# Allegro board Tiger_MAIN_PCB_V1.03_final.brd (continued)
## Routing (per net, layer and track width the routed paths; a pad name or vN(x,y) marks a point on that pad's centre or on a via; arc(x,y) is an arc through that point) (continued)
I2C_DATA3: length 2.2
  BOTTOM w0.109: R380.2 45.52,69.86 U22.95
IINA: length 6.3
  BOTTOM w0.508: R3130.1 R3131.1 R3133.1 R3132.1 90.63,94.36 CN41.2
IINA0: length 45.6
  TOP w0.406: v2(85.32,92.74) 86.58,94 89.17,94 90.73,92.44 98.79,92.44 99.52,91.7 v2(100.04,91.7) 110.53,91.7 112.15,93.32 117.8,93.32 119.17,91.94 119.17,89.04 119.56,88.64 U2529.1
  BOTTOM w0.406: v2(100.04,91.7) 99.81,91.47 R345.1 97.38,91.47 96.96,91.06 J5.1 ; R3130.2 v2(85.32,92.74)
IINA1: length 46.9
  TOP w0.406: v2(86.38,92.74) 86.85,93.21 89.08,93.21 90.49,91.8 98.49,91.8 99.15,91.14 v2(100.55,91.14) 111.19,91.14 112.68,92.63 117.63,92.63 118.52,91.74 118.52,88.81 119.33,87.99 U2529.2
  BOTTOM w0.406: R3131.2 v2(86.38,92.74) ; J5.2 95.12,90.21 95.55,89.78 96.8,89.78 97.54,90.52 R345.2 99.93,90.52 v2(100.55,91.14)
IINA2: length 39.3
  TOP w0.406: U2529.4 119.41,86.7 118.99,87.12 118.99,87.57 117.75,88.81 R3089.1 117.75,91.49 117.25,91.99 113.44,91.99 111.97,90.52 98.87,90.52 98.3,91.1 90.25,91.1 v2(88.99,92.36)
  BOTTOM w0.406: R3118.2 88.31,91.52 R3095.1 v2(88.99,92.36)
  BOTTOM w0.508: R3132.2 88.31,93.39 R3095.1
IINA3: length 38.8
  TOP w0.406: v2(86.71,91.52) 87.91,90.32 98.04,90.32 98.49,89.87 112.97,89.87 115.19,87.66 R3090.1 118.08,87.66 118.47,87.27 118.47,86.53 118.96,86.04 U2529.5
  BOTTOM w0.406: v2(86.71,91.52) R3097.2 87.36,91.52 R3095.2
  BOTTOM w0.508: R3133.2 87.36,93.38 R3095.2
IMVP8_PROCHOT*: length 4.5
  BOTTOM w0.109: U103.38 237.03,86.31 237.03,85.73 235.84,84.55 234.26,84.55 R685.1
IMVP_SVID_CLK: length 5.5
  BOTTOM w0.109: R715.1 233.6,84.06 235.74,84.06 237.37,85.69 U103.37
IMVP_SVID_DATA: length 3.8
  BOTTOM w0.109: R686.2 237.42,83.7 237.08,84.04 237.08,84.67 238.17,85.76 U103.35
INNER_MIC: length 50.2
  TOP w0.305: v2(15.54,11.1) 15.54,10.07 17.46,8.16 52.27,8.16 54.48,10.37 CN42.2 57.49,8.96 B1.1
  BOTTOM w0.203: v2(15.54,11.1) R3119.2 15.66,11.81 C2845.1 C2844.1
INT_SERIRQ: length 169.1
  TOP w0.076: 184.55,45.45 188.13,49.03 188.13,51.18 188.52,51.57 R93.1 189.08,51.57 190.41,52.9 191.83,52.9 193.08,54.15 193.08,55.56 192.97,55.67 U1.AY11
  TOP w0.102: 184.55,45.45 183.49,44.39 183.49,37.25 180.21,33.97 169.4,33.97 167.75,32.32 153.19,32.32 144.84,40.67 144.84,43.73 127.32,61.24 117,61.24 v2(116.76,61.49) ; CN16.12 72.38,66.68 v2(72.35,66.71)
  LAY6 w0.102: v2(116.76,61.49) 115.51,61.49 114.95,62.05 114.95,62.57 114.36,63.17 83.76,63.17 79.18,67.75 73.09,67.75 72.35,67.01 v2(72.35,66.71)
  BOTTOM w0.102: U22.5 65.17,68.66 66.16,69.64 71.16,69.64 72.35,68.45 v2(72.35,66.71)
ISETA: length 15.8
  TOP w0.305: R3101.2 R3100.2 R3099.2 124.44,81.78 122.69,81.78 ; 122.69,81.78 R638.2 ; 122.69,81.78 R3098.2
  TOP w0.406: R648.1 117.81,85.39 U2529.6 ; R648.1 117.7,84.15 120.08,81.78 R638.2 ; R648.1 R754.1
ISH_ALS_INT*: length 9.3
  TOP w0.076: U1.BA8 190.83,55.77 190.83,54.53 190.47,54.18 188.86,54.18 188.3,53.62 187.83,53.62 186.3,52.09 186.3,50.75 R114.2
ISH_GYRO1_IRQ*: length 11.5
  TOP w0.076: R115.2 185.49,49.11 186.24,49.11 186.5,49.37 186.5,52.03 187.83,53.35 188.28,53.35 188.93,54 190.53,54 190.99,54.46 190.99,55.35 191.03,55.39 191.03,55.4 191.16,55.53 191.16,55.95 190.86,56.26 U1.AY8
ISH_GYRO2_IRQ*: length 6.9
  TOP w0.076: U1.BB7 189.75,54.35 188.79,54.35 188.24,53.8 187.74,53.8 186.1,52.15 186.1,51.36 R113.2
ISOLATEB: length 5.1
  BOTTOM w0.102: R315.1 131.52,45.26 130.76,45.26 129.87,44.36 129.87,43.44 129.28,42.85 129.28,42.59 128.98,42.3 U9.26
ISW: length 2.7
  TOP w0.305: R3091.2 124.93,84.28 125.39,84.74 U2529.10
ITP_PMODE: length 17.3
  TOP w0.076: v2(191.47,74.95) 191.25,74.73 U1.E8
  TOP w0.109: R719.2 179.64,81.37 182.5,78.51 v2(182.5,76.55)
  LAY6 w0.102: v2(182.5,76.55) 185.36,76.55 186.87,75.04 190,75.04 190.31,75.36 191.07,75.36 v2(191.47,74.95)
KBC_FAN_SPEED: length 131.7
  TOP w0.102: v2(158.4,18.59) 158.77,18.22 C608.2 160.21,18.22 R607.2 161.48,19.49 Q47.3
  LAY6 w0.102: v2(54.74,51.93) 74.47,51.93 75.71,50.68 87.83,50.68 89.48,49.03 92.02,49.03 92.69,48.36 92.69,47.9 93.03,47.56 94.26,47.56 96.35,49.64 109.86,49.64 110.64,50.42 111.59,50.42 116.18,45.83 123.39,45.83 124.43,44.79 130.21,44.79 130.9,45.49 135.37,45.49 153.26,27.61 153.26,23.73 v2(158.4,18.59)
  BOTTOM w0.203: v2(54.74,51.93) 54.72,51.95 U22.47
L_BKLT_EN: length 82.1
  TOP w0.076: U1.R12 v2(192.81,69.01)
  TOP w0.109: U27.2 135.51,82.8 R455.1 135.52,81.97 R454.1 135.71,81.97 136.17,81.5 136.17,79.1 135.51,78.44 v2(135.51,77)
  LAY6 w0.076: v2(192.81,69.01) 192.28,68.48 183.91,68.48 183.33,69.07 181.59,69.07 181.41,69.25 176.13,69.25
  LAY6 w0.087: 176.13,69.25 173.22,69.25 171.52,70.95 167.47,70.95 166.58,70.06 155.48,70.06 152.89,67.47 144.38,67.47 141.95,65.05 135.39,65.05 v2(134.6,65.83)
  BOTTOM w0.109: v2(134.6,65.83) 134.6,71.66 135.12,72.18 135.12,76.6 v2(135.51,77)
L_BRIGHTNESS: length 88.9
  TOP w0.076: v2(192.17,69.01) 192.36,69.27 U1.R11
  TOP w0.109: Q76.1 135.94,86.02 135.54,85.62 135.54,84.62 136.56,83.6 136.56,78.79 135.91,78.14 135.91,77.21 v2(136.14,76.98)
  TOP w0.203: Q76.1 137.38,86.72 137.2,86.9 136.56,86.9 136.15,87.31 136.15,88.82 R3111.1 R3123.2
  LAY6 w0.076: v2(192.17,69.01) 192.17,68.85 191.99,68.66 183.98,68.66 183.37,69.27 181.71,69.27 181.54,69.44 176.13,69.44
  LAY6 w0.087: v2(135.18,65.85) 142.37,65.85 144.21,67.69 152.8,67.69 155.39,70.28 166.36,70.28 167.26,71.18 171.6,71.18 173.33,69.44 176.13,69.44
  BOTTOM w0.109: v2(135.18,65.85) 135.18,71.61 135.7,72.13 135.7,76.55 v2(136.14,76.98)
L_OUT+: length 7.3
  TOP w0.508: CN21.2 245.95,27.15 246.45,26.65 246.45,25.13 245.84,24.52 R628.2
L_OUT-: length 4.8
  TOP w0.508: R627.2 244.57,25.44 CN21.1
L_VDD_EN: length 87.2
  TOP w0.076: v2(192.84,67.95) 193.45,67.95 U1.U13
  LAY6 w0.076: v2(192.84,67.95) 192.49,68.3 183.76,68.3 183.19,68.87 181.49,68.87 181.29,69.08 176.39,69.08 176.27,68.96 176.13,68.96
  LAY6 w0.102: v2(133.96,65.82) 135.04,64.74 142,64.74 144.51,67.24 153.01,67.24 155.58,69.81 166.72,69.81 167.63,70.72 171.43,70.72 173.2,68.96 176.13,68.96
  BOTTOM w0.102: v2(133.96,65.82) 133.96,80.62 131.91,82.67 131.45,82.67 130.39,83.73 R440.2 129.76,85.24 129.23,85.77 U25.3
LAN_CLK_REQ*: length 100.8
  TOP w0.076: U1.AT10 191.82,58.59 v2(191.47,58.24)
  LAY6 w0.076: v2(191.47,58.24) 191.47,58.11 190.62,57.26 187.85,57.26 187.3,56.71 184.05,56.71 183.18,55.84
  LAY6 w0.102: v2(124.82,53.48) 124.88,53.54 145.88,53.54 147.6,51.81 153.98,51.81 156.61,54.44 157.85,54.44 158.62,53.68 159.53,53.68 159.67,53.82 172.48,53.82 172.75,53.55 180.89,53.55 183.18,55.84
  BOTTOM w0.102: v2(191.47,58.24) 191.09,57.86 191.09,57.86 190.97,57.74 190.26,57.74 190.06,57.95 184.14,57.95 179.38,53.18 175.02,53.18 R1.2 ; v2(124.82,53.48) 124.8,53.45 U9.16
LAN_CMT: length 1.7
  TOP w0.305: U11.21 104.22,34.02 R332.2
LAN_CMT1: length 1.6
  TOP w0.305: U11.15 104.9,39.96 104.9,39.96 R334.2
LAN_CT: length 1.7
  TOP w0.305: R331.2 104.3,31.05 U11.24
LAN_CT1: length 1.6
  TOP w0.305: U11.18 104.9,36.99 104.9,36.99 R333.2
LAN_N1: length 15.4
  TOP w0.305: v2(102.57,31.06) R331.1 ; R332.1 v2(102.57,34.03)
  TOP w0.406: C401.2 103.12,28.06 C400.2 103.12,28.63 C402.1 103.13,29.41 C399.1 103.35,30.41 R331.1 ; R334.1 R333.1 103.15,37.94 v2(102.74,37.52)
  BOTTOM w0.406: v2(102.57,31.06) 102.57,31.06 v2(102.57,34.03) 102.57,37.36 v2(102.74,37.52)
LAN_PCIE_CLK_DN: length 128.8
  TOP w0.076: v2(209.34,79.35) 209.48,79.5 209.69,79.5 209.82,79.37 209.82,78.06 209.44,77.68 209.44,77.32 209.48,77.22 209.48,77.03 209.44,76.94 209.44,76.69 209.58,76.21 209.58,76.08 209.62,76 209.87,75.74 U1.D40
  LAY6 w0.076: 189.9,79.97 189.91,79.97 189.92,79.98 194.57,79.98 195.14,80.55 196.84,80.55 198.6,82.32 199.63,82.32 200.06,81.89 202.09,81.89 202.84,82.63 204.05,82.63 206.57,80.12 207.59,80.12 208.14,79.57 209.12,79.57 v2(209.34,79.35)
  LAY6 w0.087: v2(127.06,76.13) 126.85,76.34 126.85,76.79 127.16,77.11 129.3,77.11 130.23,76.18 134.99,76.18 135.49,75.68 141.86,75.68 142.82,76.64 149.05,76.64 150.64,78.23 158.43,78.23 160.42,80.22 162.06,80.22 162.54,80.7 163.63,80.7 163.8,80.88 169.67,80.88 169.97,80.58 171.89,80.58 172.72,79.75 174.55,79.75 175.8,81 177.74,81 178.27,81.53 182.35,81.53 182.96,80.92 182.96,80.59 183.58,79.97 189.9,79.97
  BOTTOM w0.109: v2(127.06,76.13) 126.88,75.95 126.88,75.14 126.6,74.86 126.6,45.98 126.31,45.69 126.31,43.48 U9.20
LAN_PCIE_CLK_DP: length 128.8
  TOP w0.076: U1.C40 209.69,76.46 209.61,76.71 209.61,76.9 209.64,77 209.64,77.25 209.61,77.34 209.61,77.61 209.99,77.99 209.99,79.43 209.76,79.66 209.52,79.66 209.34,79.84 v2(209.34,79.95)
  LAY6 w0.076: v2(209.34,79.95) 209.12,79.74 208.21,79.74 207.66,80.29 206.63,80.29 204.12,82.8 202.77,82.8 202.02,82.05 200.13,82.05 199.7,82.48 198.53,82.48 196.77,80.72 195.07,80.72 194.5,80.15 189.92,80.15 189.91,80.15 189.9,80.15
  LAY6 w0.087: v2(126.45,76.13) 126.66,76.34 126.66,76.87 127.09,77.29 129.37,77.29 130.31,76.36 135.07,76.36 135.57,75.87 141.78,75.87 142.74,76.82 148.98,76.82 150.56,78.41 158.35,78.41 160.35,80.4 161.98,80.4 162.46,80.89 163.56,80.89 163.73,81.06 169.75,81.06 170.05,80.76 171.97,80.76 172.8,79.93 174.48,79.93 175.73,81.18 177.66,81.18 178.19,81.71 182.43,81.71 183.14,81 183.14,80.67 183.66,80.15 189.9,80.15
  BOTTOM w0.109: v2(126.45,76.13) 126.66,75.92 126.66,75.23 126.38,74.96 126.38,46.07 126.09,45.78 126.09,43.49 U9.19
LAN_PLT_RST#: length 10.6
  BOTTOM w0.203: U9.25 128.7,42.93 129.25,43.48 129.25,44.13 130.92,45.79 131.38,45.79 R317.1 132.58,45.47 134.89,45.47 135.27,45.09 136.09,45.09 136.26,44.92 U10.4
LAN_RST: length 67.2
  TOP w0.076: v2(180.09,63.97) 180.67,63.39 182.3,63.39 183.57,64.66 U1.AD1
  LAY6 w0.102: v2(180.09,63.97) 179.16,63.04 168.69,63.04 167.61,64.12 157.03,64.12 150.63,57.72 145.74,57.72 144.85,58.61 135.13,58.61 v2(134.77,58.25)
  BOTTOM w0.102: R318.2 v2(134.77,58.25)
LAN_TX0N: length 3.8
  TOP w0.097: U11.22 105.08,33.03 104.98,32.93 104.98,32.8 104.89,32.71 102.79,32.71 FIL1.1
LAN_TX0P: length 3.8
  TOP w0.097: U11.23 105.08,32.04 104.98,32.14 104.98,32.27 104.89,32.36 102.84,32.36 FIL1.4
LAN_TX1N: length 4
  TOP w0.097: FIL2.1 102.71,35.68 104.89,35.68 104.98,35.77 104.98,35.9 105.08,36 U11.19
LAN_TX1P: length 3.9
  TOP w0.097: U11.20 105.08,35.01 104.98,35.11 104.98,35.24 104.89,35.33 102.63,35.33 FIL2.4
LAN_TX2N: length 2.9
  TOP w0.097: U11.16 106.13,38.79 v2(107.06,38.79)
  BOTTOM w0.097: FIL3.4 105.79,38.66 106.93,38.66 v2(107.06,38.79)
LAN_TX2P: length 3
  TOP w0.097: v2(107.06,38.19) 106.16,38.19 U11.17
  BOTTOM w0.097: FIL3.1 105.86,38.32 106.93,38.32 v2(107.06,38.19)
LAN_TX3N: length 3
  TOP w0.097: v2(107.05,41.74) 106.15,41.74 U11.13
  BOTTOM w0.097: v2(107.05,41.74) 106.92,41.61 105.82,41.61 FIL4.4
LAN_TX3P: length 2.9
  TOP w0.097: v2(107.05,41.14) 106.14,41.14 U11.14
  BOTTOM w0.097: v2(107.05,41.14) 106.92,41.27 105.78,41.27 FIL4.1
LAN_VDDEN: length 144.5
  TOP w0.102: v2(117.35,44.28) 117.35,51.13 v2(119.75,53.53)
  LAY3 w0.102: v2(58.44,70.52) 57.8,69.88 57.8,61.11 v2(58.49,60.42)
  LAY6 w0.102: v2(171.73,54.46) 170.87,54.46 170.45,54.05 158.67,54.05 158.01,54.71 156.47,54.71 153.83,52.07 147.99,52.07 146.14,53.91 124.55,53.91 124.17,53.53 v2(119.75,53.53) 119.72,53.56 119.19,53.56 114.51,58.25 102.43,58.25 101.27,59.41 96.39,59.41 95.66,60.14 70.53,60.14 70.16,59.77 64.72,59.77 63.63,60.87 58.93,60.87 v2(58.49,60.42)
  BOTTOM w0.102: v2(58.44,70.52) 58.72,70.8 U22.124 ; v2(117.35,44.28) R309.2 U8.3 ; v2(171.73,54.46) 171.93,54.66 R142.1
LANWAKEB: length 4.6
  BOTTOM w0.102: R313.1 131.74,43.66 130.65,42.57 130.24,42.57 129.16,41.5 U9.28
LAO1_CLKN: length 20.3
  BOTTOM w0.109: CN35.8 137.87,95.67 137.76,95.56 137.43,95.56 137.27,95.4 137.27,94.88 136.85,94.46 135.87,94.46 132.62,91.21 132.62,84.56 134.04,83.14 135.23,83.14 136.02,83.92 136.37,83.92 136.46,84.01 U2526.35
LAO1_CLKP: length 20.2
  BOTTOM w0.109: U2526.34 136.46,83.61 136.37,83.7 136.11,83.7 135.33,82.92 133.95,82.92 132.4,84.47 132.4,91.3 135.78,94.67 136.75,94.67 137.05,94.97 137.05,95.5 136.87,95.67 CN35.9
LAO1_DATAN0: length 20.8
  LAY6 w0.087: v2(128.67,100.56) 128.62,100.56 128.25,100.2 128.25,98.93 136.08,91.1 136.08,90.82 v2(136.29,90.61)
  BOTTOM w0.109: CN35.24 128.87,101.47 128.76,101.36 128.59,101.36 128.48,101.25 128.48,100.76 v2(128.67,100.56) ; v2(136.29,90.61) 135.91,90.23 135.91,89.14 135.67,88.9 135.67,87.24 136.19,86.72 136.37,86.72 136.46,86.81 U2526.42
LAO1_DATAN1: length 19.4
  BOTTOM w0.109: U2526.40 136.46,86.01 136.37,85.92 135.98,85.92 134.62,87.28 134.62,90.79 136.71,92.88 142.08,92.88 143.26,94.06 143.26,95.38 143.45,95.56 143.76,95.56 143.87,95.67 CN35.2
LAO1_DATAN2: length 20.7
  BOTTOM w0.109: U2526.37 136.46,84.81 136.37,84.72 135.82,84.72 135.23,84.13 134.19,84.13 133.84,84.49 133.84,91.32 136.18,93.66 139.47,93.66 140.27,94.46 140.27,95.39 140.44,95.56 140.76,95.56 140.87,95.67 CN35.5
LAO1_DATAN3: length 20.3
  BOTTOM w0.109: U2526.32 136.46,82.81 136.37,82.72 135.94,82.72 135.52,82.3 133.8,82.3 131.88,84.22 131.88,91.56 135.28,94.95 135.28,95.41 135.43,95.56 135.76,95.56 135.87,95.67 CN35.10
LAO1_DATAP0: length 20.8
  LAY6 w0.087: v2(128.07,100.56) 128.07,98.85 135.9,91.02 135.9,90.81 v2(135.69,90.61)
  BOTTOM w0.109: CN35.23 127.87,101.47 127.98,101.36 128.15,101.36 128.26,101.25 128.26,100.76 v2(128.07,100.56) ; U2526.41 136.46,86.41 136.37,86.5 136.1,86.5 135.45,87.15 135.45,88.99 135.69,89.23 v2(135.69,90.61)
LAO1_DATAP1: length 19.4
  BOTTOM w0.109: CN35.3 142.87,95.67 143.05,95.5 143.05,94.15 141.99,93.1 136.62,93.1 134.4,90.88 134.4,87.19 135.89,85.7 136.37,85.7 136.46,85.61 U2526.39
LAO1_DATAP2: length 20.7
  BOTTOM w0.109: CN35.6 139.87,95.67 140.05,95.5 140.05,94.55 139.38,93.87 136.09,93.87 133.62,91.41 133.62,84.4 134.1,83.91 135.33,83.91 135.92,84.5 136.37,84.5 136.46,84.41 U2526.36
LAO1_DATAP3: length 20.3
  BOTTOM w0.109: CN35.11 134.87,95.85 135.06,95.66 135.06,95.04 131.66,91.65 131.66,84.13 133.71,82.08 135.61,82.08 136.03,82.5 136.37,82.5 136.46,82.41 U2526.31
LAO_CLKN: length 17.4
  LAY6 w0.087: v2(138.72,91.89) 138.51,92.1 138.51,94.83 134.47,98.88 134.47,100.36 v2(134.67,100.56)
  BOTTOM w0.109: CN35.30 134.87,101.47 134.76,101.36 134.59,101.36 134.48,101.25 134.48,100.76 v2(134.67,100.56) ; v2(138.72,91.89) 138.53,91.7 138.53,90.38 139.26,89.64 139.26,88.2 139.35,88.11 U2526.47
LAO_CLKP: length 17.4
  LAY6 w0.087: v2(138.12,91.89) 138.33,92.1 138.33,94.76 134.28,98.8 134.28,100.35 v2(134.07,100.56)
  BOTTOM w0.109: v2(134.07,100.56) 134.26,100.76 134.26,101.26 134.15,101.36 133.98,101.36 133.87,101.47 CN35.29 ; v2(138.12,91.89) 138.31,91.7 138.31,90.29 139.05,89.55 139.05,88.2 138.95,88.11 U2526.46
LAO_DATAN0: length 25.8
  BOTTOM w0.109: CN35.39 143.87,101.85 143.45,101.43 143.45,100.97 143.73,100.7 148.57,100.7 150.01,99.26 150.01,93.44 146.06,89.5 142.74,89.5 142.06,88.82 142.06,88.2 142.15,88.11 U2526.54
LAO_DATAN1: length 27.9
  BOTTOM w0.109: U2526.52 141.35,88.11 141.26,88.2 141.26,89.76 142.14,90.64 145.31,90.64 149.11,94.43 149.11,98.8 147.96,99.94 140.83,99.94 140.48,100.29 140.48,101.25 140.59,101.36 140.76,101.36 140.87,101.47 CN35.36
LAO_DATAN2: length 26.7
  BOTTOM w0.109: U2526.49 140.15,88.11 140.06,88.2 140.06,91.21 140.87,92.02 144.14,92.02 145.74,93.62 145.74,98.21 144.98,98.97 138.34,98.97 137.48,99.83 137.48,101.25 137.59,101.36 137.76,101.36 137.87,101.47 CN35.33
LAO_DATAN3: length 18.1
  LAY6 w0.087: v2(137.42,91.77) 137.21,91.98 137.21,93.04 131.46,98.8 131.46,100.36 v2(131.67,100.56)
  BOTTOM w0.109: CN35.27 131.87,101.47 131.76,101.36 131.59,101.36 131.48,101.25 131.48,100.76 v2(131.67,100.56) ; U2526.44 138.15,88.11 138.06,88.2 138.06,88.47 137.23,89.3 137.23,91.57 v2(137.42,91.77)
LAO_DATAP0: length 25.8
  BOTTOM w0.109: U2526.53 141.75,88.11 141.85,88.2 141.85,88.91 142.65,89.71 145.97,89.71 149.79,93.53 149.79,99.17 148.48,100.48 143.64,100.48 143.24,100.88 143.24,101.44 142.87,101.81 CN35.38
LAO_DATAP1: length 27.9
  BOTTOM w0.109: CN35.35 139.87,101.47 139.98,101.36 140.15,101.36 140.26,101.25 140.26,100.2 140.74,99.73 147.87,99.73 148.89,98.71 148.89,94.52 145.22,90.85 142.05,90.85 141.05,89.85 141.05,88.2 140.95,88.11 U2526.51
LAO_DATAP2: length 26.7
  BOTTOM w0.109: CN35.32 136.87,101.47 136.98,101.36 137.15,101.36 137.26,101.25 137.26,99.74 138.25,98.75 144.89,98.75 145.52,98.12 145.52,93.71 144.05,92.24 140.78,92.24 139.85,91.3 139.85,88.2 139.75,88.11 U2526.48
LAO_DATAP3: length 18.1
  LAY6 w0.087: v2(131.07,100.56) 131.28,100.36 131.28,98.72 137.03,92.97 137.03,91.98 v2(136.82,91.77)
  BOTTOM w0.109: v2(131.07,100.56) 131.26,100.76 131.26,101.26 131.15,101.36 130.98,101.36 130.87,101.47 CN35.26 ; v2(136.82,91.77) 137.01,91.57 137.01,89.21 137.85,88.38 137.85,88.2 137.75,88.11 U2526.43
LDO2-CAP: length 5.3
  BOTTOM w0.203: C444.2 10.55,23.37 12.02,23.37 13.13,22.26 U16.39
LDR: length 2.8
  TOP w0.305: U2529.11 127.17,85.39 127.42,85.14 127.42,84.31 127.78,83.96 R606.1
LED_ON: length 111.5
  TOP w0.102: R453.2 128.87,81.26 128.12,80.51 128.12,75.27 127.02,74.16 v2(127.02,72.79)
  LAY3 w0.102: v2(58.87,62.64) 58.87,73.01 57.9,73.97 57.9,83.89 v2(60.1,86.09)
  LAY6 w0.102: v2(127.02,72.79) 124.05,72.79 122.07,74.77 110.77,74.77 110.08,74.07 96.03,74.07 84.28,85.82 60.37,85.82 v2(60.1,86.09)
  BOTTOM w0.102: v2(58.87,62.64) 59.28,63.06 U22.19
LPC_CLKRUN*: length 181.1
  TOP w0.076: 190.32,53.33 191.68,53.33 192.54,54.2 192.54,54.49 192.39,54.64 192.39,56.32 192.7,56.63 U1.AW11 ; R94.2 187.72,51.17 187.72,49.27 184.64,46.19
  TOP w0.102: 181.65,36.18 183.03,37.55 183.03,44.58 184.64,46.19 ; R94.2 189.09,53.33 190.32,53.33
  TOP w0.109: 181.65,36.18 179.94,34.46 169.2,34.46 167.54,32.81 153.4,32.81 145.33,40.88 145.33,43.93 127.52,61.73 117.63,61.73 116.18,63.18 v2(115.78,63.18)
  LAY6 w0.087: v2(115.78,63.18) 115.39,63.57 84.85,63.57 78.75,69.68 63.63,69.68 62.91,68.96 48.46,68.96 v2(48.35,69.06)
  BOTTOM w0.109: U22.93 v2(48.35,69.06)
LPC_FRAME*: length 169.3
  TOP w0.076: 184.74,45.26 189.03,49.55 189.03,51.14 190.6,52.7 191.89,52.7 193.25,54.07 193.25,55.77 U1.BA12
  TOP w0.102: 184.74,45.26 183.95,44.47 183.95,37.21 182.92,36.18
  TOP w0.109: v2(70.86,69.22) 70.88,69.2 CN16.9 ; 182.92,36.18 180.44,33.7 169.52,33.7 167.86,32.04 153.08,32.04 144.56,40.56 144.56,43.61 127.2,60.96 116.5,60.96 115.77,61.69 v2(115.77,61.97)
  LAY6 w0.087: v2(70.86,69.22) 78.57,69.22 84.42,63.37 114.86,63.37 115.77,62.47 v2(115.77,61.97)
  BOTTOM w0.109: U22.6 65.25,68.26 66.22,69.22 v2(70.86,69.22)
LPC_LAD[0]: length 178.5
  TOP w0.076: 185.57,44.74 185.57,44.76 189.71,48.9 189.71,50.66 190.92,51.87 192.06,51.87 193.96,53.77 193.96,54.5 194.11,54.65 194.11,54.93 194.06,55.05 194.06,55.19 194.12,55.42 194.12,55.54 194.05,55.74 193.95,55.86 193.85,55.97 U1.AY13
  TOP w0.102: 185.57,44.74 185.57,37.05 184.69,36.18
  TOP w0.109: v2(70.45,66.8) 70.38,66.73 CN16.8 ; v2(69.53,64.14) 69.53,63.14 72,60.67 83.95,60.67 91.9,68.62 106.04,68.62 114.71,59.95 126.79,59.95 143.55,43.19 143.55,39.97 152.6,30.91 168.19,30.91 169.94,32.67 181.18,32.67 184.69,36.18
  BOTTOM w0.109: v2(69.53,64.14) 70.45,65.06 v2(70.45,66.8) 69.77,67.47 66.81,67.47 66,66.66 U22.10
LPC_LAD[1]: length 174.5
  TOP w0.076: U1.BA13 193.85,55.27 193.58,55 193.58,53.89 191.98,52.29 190.86,52.29 189.38,50.81 189.38,49.23 185.07,44.93
  TOP w0.102: 183.7,36.18 184.96,37.44 184.96,44.81 185.07,44.93
  TOP w0.109: v2(69.99,68.5) 70.01,68.47 70.01,66.31 69.88,66.18 CN16.7 69.88,64.98 73.68,61.18 83.74,61.18 91.69,69.13 106.25,69.13 114.92,60.46 127,60.46 144.06,43.4 144.06,40.35 152.87,31.54 168.07,31.54 169.73,33.2 180.72,33.2 183.7,36.18
  BOTTOM w0.109: v2(69.99,68.5) 69.2,67.71 66.48,67.71 65.83,67.06 U22.9
LPC_LAD[2]: length 174.3
  TOP w0.076: U1.BB13 193.76,54.73 193.76,53.82 192.04,52.1 190.91,52.1 189.54,50.73 189.54,49.06 185.25,44.76 185.25,44.75
  TOP w0.102: 184.18,36.18 185.25,37.24 185.25,44.75
  TOP w0.109: 184.18,36.18 180.94,32.93 169.84,32.93 168.18,31.28 152.76,31.28 143.79,40.24 143.79,43.29 126.89,60.2 114.81,60.2 106.15,68.87 91.8,68.87 83.85,60.92 73.35,60.92 69.38,64.89 CN16.6 69.38,66.12 69.16,66.34 69.16,68.31 v2(69.37,68.51)
  BOTTOM w0.109: v2(69.37,68.51) 68.81,67.95 66.12,67.95 65.62,67.46 U22.8
LPC_LAD[3]: length 178.2
  TOP w0.076: 184.89,45.11 189.2,49.42 189.2,50.97 190.73,52.51 191.94,52.51 193.41,53.98 193.41,55.36 193.58,55.53 193.58,55.95 193.28,56.26 U1.AY12
  TOP w0.102: 183.32,36.18 184.47,37.33 184.47,44.7 184.89,45.11
  TOP w0.109: 183.32,36.18 180.62,33.48 169.61,33.48 167.95,31.82 152.99,31.82 144.34,40.47 144.34,43.52 127.11,60.75 115.04,60.75 106.37,69.41 91.57,69.41 83.62,61.46 74.16,61.46 v2(71.46,64.17) ; v2(68.61,68.52) 68.88,68.25 CN16.5
  BOTTOM w0.109: v2(71.46,64.17) 71.17,64.45 71.17,68.09 70.29,68.97 69.05,68.97 v2(68.61,68.52) 66.04,68.52 65.38,67.86 U22.7
LPCPD#: length 2.4
  BOTTOM w0.109: U22.17 64.02,63.86 R488.2
M_B_A0: length 54.6
  TOP w0.076: 212.47,51.03 212.14,51.37 212.14,53.19 212.14,53.68 212.04,53.78 212.04,55.03 212.3,55.3 U1.BA46
  TOP w0.102: v2(214.64,45.39) 212.59,47.44 212.59,50.91 212.47,51.03
  TOP w0.153: 203.62,15.95 CN1.144
  TOP w0.165: v2(206.39,17.76) 205.43,17.76 203.62,15.95
  LAY6 w0.076: v2(214.64,45.39) 214.86,45.17
  LAY6 w0.137: v2(206.39,17.76) 205.96,18.19 205.96,19.4 206.37,19.81 206.37,25.83 209.85,29.31 209.85,34.13 210.36,34.64 210.55,34.64 211,34.19 211.2,34.19 211.39,34.38 211.39,34.58 210.94,35.03 210.94,35.22 211.13,35.42 211.33,35.42 211.78,34.97 211.97,34.97 212.17,35.16 212.17,35.35 211.71,35.81 211.71,36 211.91,36.2 212.1,36.2 212.56,35.74 212.75,35.74 212.95,35.94 212.95,36.13 212.49,36.58 212.49,36.78 212.69,36.97 212.88,36.97 213.33,36.52 213.53,36.52 213.72,36.71 213.72,36.91 213.27,37.36 213.27,37.55 214.86,39.15 214.86,45.17
M_B_A1: length 55.6
  TOP w0.076: U1.AY46 212.4,55.87 212.51,55.77 212.58,55.55 212.58,55.42 212.52,55.19 212.52,55.05 212.57,54.93 212.57,54.67 212.37,54.47 212.37,53.92 212.47,53.82 212.47,53.79 212.47,53.79 212.47,53.33 212.47,51.59 212.98,51.08 212.98,51.06
  TOP w0.102: 212.98,51.06 213.01,51.03 213.01,49 v2(214.66,47.34)
  TOP w0.165: v2(206.74,18.86) 206.36,19.23 CN1.133
  LAY6 w0.076: 215.54,45.27 215.21,45.6 215.21,46.8 v2(214.66,47.34)
  LAY6 w0.137: 215.54,45.27 215.54,37.07 215.4,36.93 215.4,35.63 215.33,35.56 215.13,35.56 214.84,35.85 214.65,35.85 214.45,35.65 214.45,35.46 214.74,35.17 214.74,34.98 214.09,34.33 214.09,34.14 214.8,33.43 214.8,33.24 214.6,33.05 214.41,33.05 213.71,33.75 213.51,33.75 213.32,33.55 213.32,33.36 214.02,32.66 214.02,32.46 213.83,32.27 213.63,32.27 212.93,32.97 212.74,32.97 212.54,32.78 212.54,32.58 213.24,31.88 213.24,31.69 213.05,31.49 212.86,31.49 212.15,32.19 211.96,32.19 211.77,32 211.77,31.81 212.47,31.11 212.47,30.91 212.27,30.72 212.08,30.72 211.38,31.42 211.18,31.42 210.86,31.09 210.86,29.1 207.28,25.52 207.28,22.93 206.95,22.6 206.95,19.07 v2(206.74,18.86)
M_B_A2: length 55.5
  TOP w0.076: 213.26,51.03 213.26,51.06 212.63,51.68 212.63,53.4 212.63,53.4 212.63,53.73 212.63,53.73 212.63,53.89 212.53,53.99 212.53,54.4 212.74,54.6 212.74,54.97 212.72,55 212.69,55.08 212.69,55.2 212.75,55.41 212.75,55.56 212.7,55.72 212.7,56.14 U1.AY47
  TOP w0.102: v2(214.66,47.99) 213.26,49.4 213.26,51.03
  TOP w0.153: CN1.132 206.62,15.91
  TOP w0.165: 206.62,15.91 207,16.3 v2(207.14,16.3)
  LAY6 w0.076: v2(214.66,47.99) 215.15,47.99 215.45,47.7 215.45,45.65 215.84,45.26
  LAY6 w0.137: 215.84,45.26 215.84,35.35 215.44,34.95 215.44,33.04 212.61,30.21 212.61,30.02 212.91,29.72 212.91,29.5 212.76,29.35 212.5,29.35 212.22,29.63 212.02,29.63 211.83,29.44 211.83,29.24 212.15,28.92 212.15,28.73 211.96,28.53 211.76,28.53 211.44,28.85 211.25,28.85 211.05,28.66 211.05,28.47 211.37,28.15 211.37,27.95 211.18,27.76 210.99,27.76 210.67,28.08 210.47,28.08 210.28,27.88 210.28,27.69 210.6,27.37 210.6,27.18 210.4,26.98 210.21,26.98 209.89,27.3 209.7,27.3 209.5,27.11 209.5,26.91 209.82,26.59 209.82,26.4 209.63,26.21 209.43,26.21 209.11,26.53 208.92,26.53 208.73,26.33 208.73,26.14 209.05,25.82 209.05,25.62 208.85,25.43 208.66,25.43 208.34,25.75 208.14,25.75 207.75,25.36 207.75,18.51 206.76,17.52 206.76,16.68 v2(207.14,16.3)
M_B_A3: length 53.8
  TOP w0.076: U1.BB46 212.2,54.72 212.2,53.85 212.3,53.75 212.3,53.26 212.3,53.26 212.3,51.47 212.74,51.03
  TOP w0.102: 212.74,51.03 212.78,50.99 212.78,47.91 v2(214.64,46.05)
  TOP w0.165: CN1.131 206.86,19.81 v2(207.35,19.33)
  LAY6 w0.076: 215.27,45.18 214.99,45.46 214.99,45.7 v2(214.64,46.05)
  LAY6 w0.137: 215.27,45.18 215.27,37.51 215.14,37.39 214.95,37.39 214.46,37.88 214.26,37.88 214.07,37.68 214.07,37.49 214.56,37 214.56,36.8 213.62,35.86 213.62,35.67 214.1,35.19 214.1,34.99 213.9,34.8 213.71,34.8 213.23,35.28 213.04,35.28 212.84,35.08 212.84,34.89 213.32,34.41 213.32,34.22 213.13,34.02 212.93,34.02 212.46,34.5 212.26,34.5 212.07,34.31 212.07,34.11 212.55,33.64 212.55,33.44 212.35,33.25 212.16,33.25 211.68,33.73 211.49,33.73 211.29,33.53 211.29,33.34 211.77,32.86 211.77,32.67 211.58,32.47 211.38,32.47 210.9,32.95 210.71,32.95 210.32,32.56 210.32,29.16 206.81,25.65 206.81,23.02 206.66,22.87 206.66,19.46 206.28,19.08 206.28,18.65 206.47,18.46 207.03,18.46 207.35,18.78 v2(207.35,19.33)
M_B_A4: length 54.7
  TOP w0.076: U1.BA47 213.19,55.58 213.19,55.35 213.2,55.34 213.2,55.34 213.2,55.34 213.23,55.25 213.23,55.05 213.2,54.96 213.2,54.56 213.32,54.43 213.32,53.82 213.42,53.73 213.42,53.33 213.52,53.23 213.52,53.2 213.53,53.19 213.53,51.99 214.03,51.5 214.03,51.49 214.03,50.79
  TOP w0.102: 214.03,50.79 213.52,50.27 213.52,49.56 213.99,49.09 214.46,49.09 v2(214.66,49.29)
  TOP w0.153: v2(207.19,16.94) 207.19,17.19 207.33,17.33 207.64,17.33 207.78,17.19 207.78,16.76 207.62,16.6 CN1.128
  LAY6 w0.076: v2(214.66,49.29) 214.95,49.58 215.44,49.58 215.64,49.37 215.64,45.74 216.08,45.3
  LAY6 w0.137: v2(207.19,16.94) 207.19,17.6 208.07,18.47 208.07,22.98 208.21,23.12 208.21,24.06 213.47,29.32 213.47,30.48 213.71,30.72 213.9,30.72 214.24,30.38 214.44,30.38 214.63,30.57 214.63,30.77 214.29,31.11 214.29,31.3 214.48,31.49 214.68,31.49 215.02,31.15 215.21,31.15 215.41,31.35 215.41,31.54 215.07,31.88 215.07,32.08 215.26,32.27 215.45,32.27 215.79,31.93 215.99,31.93 216.18,32.12 216.18,32.32 215.84,32.66 215.84,32.85 216.39,33.4 216.39,33.88 216.25,34.02 216.03,34.02 215.89,34.16 215.89,34.43 216.03,34.57 216.25,34.57 216.39,34.71 216.39,36.44 216.08,36.75 216.08,45.3
M_B_A5: length 55.5
  TOP w0.076: U1.AY48 213.43,55.92 213.43,55.76 213.36,55.57 213.36,55.37 213.4,55.28 213.4,55.02 213.36,54.93 213.36,54.67 213.49,54.55 213.49,53.89 213.58,53.79 213.58,53.4 213.7,53.29 213.7,52.08 214.11,51.68 214.11,51.66 214.21,51.56 214.21,50.58
  TOP w0.102: v2(214.66,49.94) 214.42,49.94 214.21,50.16 214.21,50.58
  TOP w0.153: 208.11,16.06 CN1.126
  TOP w0.165: v2(208.6,16.37) 208.43,16.37 208.11,16.06
  LAY6 w0.076: v2(214.66,49.94) 214.99,50.27 215.65,50.27 215.91,50.02 215.91,45.82 216.44,45.28
  LAY6 w0.137: v2(208.6,16.37) 208.31,16.37 208.15,16.2 208.15,14.52 207.78,14.16 207.02,14.16 206.85,14.33 206.85,14.56 207,14.71 207.43,14.71 207.62,14.91 207.62,17.52 208.39,18.28 208.39,22.32 208.7,22.64 208.7,23.94 216.86,32.09 216.86,36.55 216.44,36.97 216.44,45.28
M_B_A6: length 54.2
  TOP w0.076: v2(214.66,51.9) 214.44,51.9 214.05,52.28 214.05,53.46 213.94,53.58 213.94,53.92 213.9,53.96 213.9,54.98 213.63,55.25 U1.BA48
  TOP w0.153: CN1.127 207.86,18.3 208.49,17.67 209.15,17.67 209.35,17.88 209.35,18.27 v2(208.91,18.72)
  LAY6 w0.076: 217.12,45.17 216.31,45.98 216.31,51.12 215.54,51.9 v2(214.66,51.9)
  LAY6 w0.137: 217.12,45.17 217.12,37.31 217.75,36.69 217.75,30.44 217.36,30.06 217.17,30.06 216.74,30.49 216.54,30.49 216.35,30.3 216.35,30.1 216.78,29.67 216.78,29.47 216.59,29.28 216.39,29.28 215.96,29.71 215.77,29.71 215.57,29.52 215.57,29.33 216.01,28.89 216.01,28.7 215.81,28.5 215.62,28.5 215.18,28.94 214.99,28.94 214.8,28.74 214.8,28.55 215.23,28.12 215.23,27.92 209.56,22.25 209.56,18.73 209.39,18.56 209.06,18.56 v2(208.91,18.72)
M_B_A7: length 57.5
  TOP w0.076: U1.AP48 v2(214.33,59.51)
  TOP w0.153: CN1.122 209.11,16.88 209.26,17.03 210.03,17.03 210.29,16.76 210.29,16.32 210.16,16.19 209.83,16.19 v2(209.67,16.35)
  LAY6 w0.076: 217.9,45.32 217.36,45.87 217.36,51.78 215.07,54.07 215.07,57 214.71,57.35 214.71,59.14 v2(214.33,59.51)
  LAY6 w0.137: v2(209.67,16.35) 209.94,16.09 210.44,16.09 210.61,16.25 210.61,16.63 210.47,16.77 210.12,16.77 210,16.89 210,17.17 210.14,17.3 210.66,17.3 210.8,17.44 210.8,17.86 210.65,18.02 210.3,18.02 210.1,18.22 210.1,21.41 218.64,29.94 218.64,36.69 217.9,37.42 217.9,45.32
M_B_A8: length 52.6
  TOP w0.076: U1.BB48 213.63,54.64 213.65,54.62 213.65,53.96 213.75,53.86 213.75,53.47 213.86,53.36 213.86,52.15 214.27,51.75 214.27,51.73 214.37,51.63 214.37,51.63 214.44,51.57 214.44,51.47 v2(214.66,51.25)
  TOP w0.153: v2(208.89,19.39) 208.65,19.39 208.36,19.68 CN1.125
  LAY6 w0.076: v2(214.66,51.25) 215.53,51.25 216.14,50.64 216.14,45.86 216.72,45.28
  LAY6 w0.137: 216.72,45.28 216.72,37.21 217.3,36.62 217.3,31.89 214.09,28.68 214.09,28.48 214.52,28.06 214.52,27.87 214.32,27.67 214.13,27.67 213.71,28.1 213.51,28.1 213.32,27.9 213.32,27.71 213.74,27.28 213.74,27.09 213.55,26.9 213.35,26.9 212.93,27.32 212.74,27.32 212.54,27.12 212.54,26.93 212.96,26.51 212.96,26.32 212.77,26.12 212.58,26.12 212.15,26.54 211.96,26.54 211.76,26.35 211.76,26.15 212.19,25.73 212.19,25.54 211.99,25.34 211.8,25.34 211.38,25.77 211.18,25.77 210.99,25.57 210.99,25.38 211.41,24.96 211.41,24.76 211.22,24.57 211.02,24.57 210.6,24.99 210.41,24.99 210.21,24.8 210.21,24.6 210.63,24.18 210.63,23.99 210.44,23.79 210.25,23.79 209.82,24.21 209.63,24.21 209.14,23.72 209.14,22.74 209.28,22.6 209.28,19.77 v2(208.89,19.39)
M_B_A9: length 52.7
  TOP w0.076: U1.AP50 v2(215.25,59.51)
  TOP w0.153: CN1.121 209.36,18.87 210.14,18.09 210.86,18.09 211.05,18.28 211.05,18.83 v2(210.57,19.31)
  LAY6 w0.076: 218.5,45.73 218.5,46.64 218.51,46.66 218.51,51.86 215.29,55.08 215.29,57.01 214.88,57.42 214.88,59.14 v2(215.25,59.51)
  LAY6 w0.137: v2(210.57,19.31) 210.99,19.73 210.99,21.62 219.08,29.71 219.08,45.15 218.5,45.73
M_B_A10: length 54.9
  TOP w0.076: U1.AW46 212.4,56.59 212.21,56.4 212.11,56.19 212.11,55.7 211.87,55.46 211.87,53.71 211.97,53.62 211.97,53.12 211.97,51.26 212.2,51.03
  TOP w0.102: v2(212,46.71) 212.4,47.11 212.4,50.83 212.2,51.03
  TOP w0.153: CN1.146 v2(201.11,15.12)
  LAY6 w0.076: 212.46,44.67 212,45.14 v2(212,46.71)
  LAY6 w0.137: v2(201.11,15.12) 201.05,15.05 201.05,14.14 201.25,13.94 201.71,13.94 201.85,14.08 201.85,15.05 201.99,15.18 202.26,15.18 202.4,15.05 202.4,14.08 202.54,13.94 202.96,13.94 203.21,14.18 203.21,16.02 202.22,17.01 202.22,26.55 206.79,31.12 206.79,34.82 212.46,40.5 212.46,44.67
M_B_A11: length 58.1
  TOP w0.076: U1.AN48 v2(214.33,60.15)
  TOP w0.153: CN1.120 209.62,15.16
  TOP w0.165: 209.62,15.16 v2(209.61,15.17)
  LAY6 w0.076: v2(214.33,60.15) 214.08,60.15 213.88,59.94 213.88,57.51 214.71,56.67 214.71,54.05 217.11,51.65 217.11,45.55 217.49,45.17
  LAY6 w0.137: v2(209.61,15.17) 209.86,14.92 210.08,14.92 210.29,14.7 210.29,14.19 210.05,13.95 208.83,13.95 208.65,14.13 208.65,14.61 209.11,15.07 209.11,16.45 208.4,17.17 208.4,17.62 208.92,18.14 209.42,18.14 209.82,18.55 209.82,21.75 218.17,30.09 218.17,36.69 217.49,37.36 217.49,45.17
M_B_A12: length 57
  TOP w0.076: U1.AN50 v2(215.25,60.15)
  TOP w0.153: v2(210.56,18.55) 210.53,18.52 210.19,18.52 209.86,18.85 CN1.119
  LAY6 w0.076: 218.92,45.68 218.92,51.78 215.61,55.09 215.61,59.78 v2(215.25,60.15)
  LAY6 w0.137: v2(210.56,18.55) 210.65,18.46 211.12,18.46 211.26,18.6 211.26,21.13 219.58,29.45 219.58,31.64 219.71,31.78 220.09,31.78 220.22,31.92 220.22,32.19 220.09,32.33 219.71,32.33 219.58,32.46 219.58,32.74 219.71,32.88 220.09,32.88 220.22,33.01 220.22,33.29 220.09,33.42 219.71,33.42 219.58,33.56 219.58,33.84 219.71,33.97 220.09,33.97 220.22,34.11 220.22,34.38 220.09,34.52 219.71,34.52 219.58,34.66 219.58,34.93 219.71,35.07 220.09,35.07 220.22,35.21 220.22,35.48 220.09,35.62 219.71,35.62 219.58,35.76 219.58,36.03 219.71,36.17 220.09,36.17 220.22,36.3 220.22,36.58 220.09,36.72 219.71,36.72 219.58,36.85 219.58,45.03 218.92,45.68
M_B_A13: length 52.2
  TOP w0.076: U1.BA43 210.38,55.57 210.38,55.33 210.37,55.3 210.33,55.2 210.33,55.09 210.38,54.96 210.38,54.71 210.38,54.7 210.38,54.57 210.24,54.44 210.24,53.94 210.51,53.68 210.51,53.61 210.98,53.14 210.98,52.71 210.98,52.71 210.98,51.76 210.83,51.6 210.83,51.03
  TOP w0.102: v2(210.42,48.85) 210.66,48.85 210.83,49.02 210.83,51.03
  TOP w0.153: v2(199.71,17.5) 199.55,17.5 199.12,17.06 198.54,17.06 198.38,16.91 198.38,16.77 198.23,16.62 197.92,16.62 197.77,16.77 197.77,16.91 197.62,17.06 197.24,17.06 196.93,16.76 196.93,15.91 197.17,15.67 197.97,15.67 198.11,15.53 CN1.158
  LAY6 w0.076: 211.14,44.47 211,44.61 211,48.6 210.75,48.85 v2(210.42,48.85)
  LAY6 w0.137: v2(199.71,17.5) 199.98,17.5 200.13,17.65 200.13,21.6 199.94,21.79 199.94,27.16 204.72,31.94 204.72,35.37 211.14,41.79 211.14,44.47
M_B_ACT_N: length 54.9
  TOP w0.076: U1.AN53 v2(217.08,60.15)
  TOP w0.153: 211.11,15.69 CN1.114
  TOP w0.165: 211.11,15.69 211.36,15.93 211.56,15.93 v2(211.65,15.85)
  LAY6 w0.076: 221.7,50.27 218.55,53.42 218.55,55.51 216.7,57.36 216.7,59.77 v2(217.08,60.15)
  LAY6 w0.137: 221.7,50.27 221.72,50.25 221.72,29.53 212.83,20.65 212.83,18.93 210.97,17.06 210.97,15.92 211.14,15.74 211.55,15.74 v2(211.65,15.85)
M_B_BG0: length 56.4
  TOP w0.076: v2(216.16,59.51) 215.78,59.89 U1.AP52
  TOP w0.153: v2(211.87,18.58) 211.74,18.58 211.07,19.25 211.07,20.93 210.86,21.13 CN1.115
  LAY6 w0.076: 221,50.6 218.22,53.38 218.22,55.6 216.51,57.31 216.51,59.16 v2(216.16,59.51)
  LAY6 w0.137: 221,50.6 221.3,50.3 221.3,49.32 221.17,49.18 220.73,49.18 220.59,49.04 220.59,48.77 220.73,48.63 221.17,48.63 221.3,48.49 221.3,48.22 221.17,48.08 220.65,48.08 220.52,47.94 220.52,47.67 220.65,47.53 221.17,47.53 221.3,47.39 221.3,47.12 221.17,46.98 220.65,46.98 220.52,46.85 220.52,46.57 220.65,46.43 221.17,46.43 221.3,46.3 221.3,46.02 221.17,45.89 220.65,45.89 220.52,45.75 220.52,45.47 220.65,45.34 221.17,45.34 221.3,45.2 221.3,29.76 212.51,20.98 212.51,19.22 v2(211.87,18.58)
M_B_BG1: length 56.6
  TOP w0.076: U1.AN52 215.77,60.54 v2(216.16,60.15)
  TOP w0.153: v2(211.83,19.29) 211.61,19.29 211.36,19.53 CN1.113
  LAY6 w0.076: 220.87,44.2 219.36,45.72 219.36,51.67 215.78,55.25 215.78,59.77 v2(216.16,60.15)
  LAY6 w0.137: 220.87,44.2 220.87,42.39 220.69,42.2 220.34,42.2 220.2,42.07 220.2,41.79 220.34,41.65 220.73,41.65 220.87,41.52 220.87,41.24 220.73,41.11 220.21,41.11 220.07,40.97 220.07,40.69 220.21,40.56 220.73,40.56 220.87,40.42 220.87,40.14 220.73,40.01 220.21,40.01 220.07,39.87 220.07,39.6 220.21,39.46 220.73,39.46 220.87,39.32 220.87,39.05 220.73,38.91 220.21,38.91 220.07,38.77 220.07,38.5 220.21,38.36 220.73,38.36 220.87,38.22 220.87,37.95 220.73,37.81 220.21,37.81 220.07,37.68 220.07,37.4 220.21,37.26 220.73,37.26 220.87,37.13 220.87,31.86 220.02,31.01 220.02,29.3 212.25,21.53 212.25,19.71 v2(211.83,19.29)
M_B_BS0: length 53.1
  TOP w0.076: 211.4,51.03 211.4,51.25 211.48,51.32 211.48,52.92 211.48,52.92 211.48,53.38 211.38,53.48 211.38,53.48 211.38,53.62 211.38,54.72 U1.BB44
  TOP w0.102: 211.4,51.03 211.4,48.44 211.77,48.07 v2(212,48.07)
  TOP w0.153: v2(201.1,16.92) 201.26,16.76 202.33,16.76 202.67,17.1 202.67,18 202.46,18.22 200.59,18.22 200.11,17.75 CN1.150
  LAY6 w0.076: v2(212,48.07) 211.53,47.61 211.53,45.17 212.11,44.6
  LAY6 w0.137: 212.11,44.6 212.11,40.81 206.3,35.01 206.3,31.29 201.76,26.74 201.76,17.14 201.54,16.92 v2(201.1,16.92)
M_B_BS1: length 55.2
  TOP w0.076: 211.59,51.03 211.59,51.15 211.64,51.2 211.64,52.99 211.64,53.45 211.54,53.55 211.54,55.21 U1.BA44
  TOP w0.102: v2(212,48.73) 211.75,48.73 211.59,48.89 211.59,51.03
  TOP w0.153: CN1.145 201.36,20.84 201.47,20.73 201.88,20.73 202.04,20.89 202.04,22.06 202.19,22.21 202.82,22.21 202.95,22.08 202.95,19.44 202.77,19.26 202.48,19.26 202.32,19.41 202.32,19.91 202.17,20.06 201.86,20.06 201.71,19.91 201.71,19.41 201.56,19.26 201.1,19.26 v2(200.91,19.45)
  LAY6 w0.076: v2(212,48.73) 212,48.86 211.78,49.08 211.56,49.08 211.37,48.89 211.37,44.96 211.76,44.56
  LAY6 w0.137: v2(200.91,19.45) 201.21,19.45 201.33,19.57 201.33,21.89 201.19,22.03 200.99,22.03 200.86,22.16 200.86,22.44 200.99,22.58 201.19,22.58 201.33,22.71 201.33,22.99 201.19,23.12 200.99,23.12 200.86,23.26 200.86,23.54 200.99,23.67 201.19,23.67 201.33,23.81 201.33,24.08 201.19,24.22 200.99,24.22 200.86,24.36 200.86,24.63 200.99,24.77 201.19,24.77 201.33,24.91 201.33,25.18 201.19,25.32 200.99,25.32 200.86,25.46 200.86,25.73 200.99,25.87 201.19,25.87 201.33,26.01 201.33,26.92 205.83,31.43 205.83,35.21 211.76,41.14 211.76,44.56
M_B_CAS_N: length 56.2
  TOP w0.076: 211.02,51.03 211.02,51.52 211.15,51.65 211.15,52.78 211.15,52.78 211.15,53.21 211.03,53.33 211.03,54.41 210.84,54.59 210.84,54.97 210.86,55 210.89,55.08 210.89,55.2 210.83,55.41 210.83,55.56 210.88,55.72 210.88,55.9 210.81,56.06 210.81,56.16 U1.AY43
  TOP w0.102: v2(210.42,48.2) 210.84,47.79 210.84,45.22 210.94,45.12 211.28,45.12 211.41,45.25 211.41,47.68 211.02,48.07 211.02,51.03
  TOP w0.153: 198.62,15.94 CN1.156
  TOP w0.165: 198.62,15.94 198.99,16.32 v2(199.64,16.32)
  LAY6 w0.076: 210.81,44.34 210.81,47.82 v2(210.42,48.2)
  LAY6 w0.137: 210.81,44.34 210.81,42.18 204.3,35.67 204.3,32.24 199.43,27.37 199.43,21.81 199.85,21.39 199.85,18.86 199.24,18.25 199.24,16.72 199.64,16.33 v2(199.64,16.32)
M_B_CB0: length 3.1
  TOP w0.102: CN1.92 216.62,15.25 v2(216.11,15.75)
  BOTTOM w0.254: R490.2 216.62,15.75 v2(216.11,15.75)
M_B_CB1: length 2.9
  TOP w0.102: CN1.91 v2(216.86,20.22)
  BOTTOM w0.102: R492.2 216.86,21.28 v2(216.86,20.22)
M_B_CB2: length 5.4
  TOP w0.102: CN1.101 214.36,20.29 v2(213.4,19.33)
  BOTTOM w0.102: R493.2 214.25,20.18 v2(213.4,19.33)
M_B_CB3: length 2.1
  TOP w0.102: CN1.105 v2(213.36,20.61)
  BOTTOM w0.102: R494.2 213.36,21.33 v2(213.36,20.61)
M_B_CB4: length 4.8
  TOP w0.102: CN1.88 217.62,15.77 216.47,16.92 v2(216.11,16.92)
  BOTTOM w0.254: v2(216.11,16.92) 216.77,16.92 R495.2
M_B_CB5: length 2.9
  TOP w0.102: CN1.87 v2(217.86,20.22)
  BOTTOM w0.102: v2(217.86,20.22) 217.86,21.31 R496.2
M_B_CB6: length 2.1
  TOP w0.102: CN1.100 v2(214.62,15.16)
  BOTTOM w0.254: R497.2 215.13,15.16 v2(214.62,15.16)
M_B_CB7: length 4
  TOP w0.102: CN1.104 213.62,16.42 v2(213.11,16.92)
  BOTTOM w0.254: R501.2 212.45,16.92 v2(213.11,16.92)
M_B_CKE<0>: length 52.6
  TOP w0.076: U1.AN56 v2(218.91,60.15)
  TOP w0.153: CN1.109 212.36,23.14
  TOP w0.165: 212.36,23.14 212.36,24.99 212.72,25.34 213.28,25.34 213.5,25.12 213.5,24.84 213.65,24.68 213.98,24.68 214.16,24.86 214.16,25.18 214.32,25.34 214.66,25.34 214.82,25.18 214.82,24.84 214.97,24.68 215.3,24.68 215.48,24.86 215.48,25.18 215.65,25.34 215.98,25.34 216.14,25.18 216.14,24.84 216.3,24.68 216.63,24.68 216.81,24.86 216.81,25.18 216.97,25.34 217.3,25.34 217.47,25.18 217.47,24.84 217.62,24.68 217.95,24.68 218.13,24.86 218.13,25.18 218.29,25.34 v2(219.18,25.34)
  LAY6 w0.076: 222.81,49.87 218.93,53.76 218.93,56.13 218.55,56.5 218.55,59.8 v2(218.91,60.15)
  LAY6 w0.137: 222.81,49.87 222.98,49.7 222.98,29.14 v2(219.18,25.34)
M_B_CKE<1>: length 52.2
  TOP w0.076: U1.AP55 v2(217.99,59.51)
  TOP w0.153: CN1.110 212.11,17.29 v2(214.05,19.22)
  LAY6 w0.076: 222.18,50.19 218.76,53.61 218.76,55.65 218.34,56.07 218.34,59.16 v2(217.99,59.51)
  LAY6 w0.137: v2(214.05,19.22) 214.05,21.22 222.18,29.35 222.18,50.19
M_B_CLK_DDR_DN*<0>: length 54.3
  TOP w0.076: U1.AN45 v2(212.51,60.15)
  TOP w0.102: v2(204.36,19.45) 204.6,19.21 204.89,19.21 205.17,19.49 205.17,20.78 204.86,21.09 CN1.139
  LAY6 w0.076: v2(212.51,60.15) 212.51,60.03 212.31,59.84 212.12,59.84 211.96,59.67 211.96,57.27 212.17,57.06 212.17,56.03 212.1,55.95 211.82,55.95 211.64,55.77 211.64,55.48 211.8,55.32 212.07,55.32 212.16,55.23 212.16,55.08 212.1,55.01 211.77,55.01 211.6,54.84 211.6,54.55 211.77,54.38 212.1,54.38 212.17,54.3 212.17,54.15 212.1,54.07 211.77,54.07 211.6,53.9 211.6,53.61 211.77,53.44 212.16,53.44 212.24,53.36 212.24,53.21 212.16,53.14 211.77,53.14 211.6,52.96 211.6,52.67 211.77,52.5 212,52.5 212.17,52.33 212.17,51.87 213.06,50.98 213.06,45.28 213.06,45.13 213.1,45.1 213.1,45.09 213.11,45.08
  LAY6 w0.087: v2(204.36,19.45) 204.6,19.21 204.71,19.21 204.85,19.36 204.85,20.78 204.23,21.4 204.23,22.89 204.85,23.51 204.85,26.35 208.36,29.85 208.36,34.58 210.08,36.3 210.09,36.3 213.67,39.89 213.67,44.52 213.11,45.08
M_B_CLK_DDR_DN*<1>: length 53.4
  TOP w0.076: v2(213.42,60.15) 213.03,60.54 U1.AN46 ; v2(205.62,16.33) 205.39,16.11 205.07,16.11 204.78,15.82 204.78,15.08 204.62,14.91 CN1.140
  LAY6 w0.076: v2(213.42,60.15) 213.25,59.98 213.06,59.98 212.86,59.78 212.86,56.51 214.05,55.32 214.05,51.18 213.91,51.05 213.91,45.16
  LAY6 w0.087: v2(205.62,16.33) 205.75,16.2 206.1,16.2 206.17,16.26 206.17,16.93 205.24,17.86 205.24,22.13 205.54,22.43 205.54,26.04 209.12,29.62 209.12,34.39 211.03,36.3 211.04,36.3 214.22,39.47 214.22,44.86 213.91,45.16
M_B_CLK_DDR_DP<0>: length 54.3
  TOP w0.076: U1.AP45 212.13,59.89 v2(212.51,59.51)
  TOP w0.102: v2(204.36,18.86) 204.52,19.02 204.97,19.02 205.36,19.41 CN1.137
  LAY6 w0.076: v2(212.51,59.51) 212.35,59.67 212.19,59.67 212.12,59.6 212.12,57.34 212.34,57.13 212.34,55.96 212.16,55.79 211.89,55.79 211.8,55.7 211.8,55.55 211.87,55.48 212.14,55.48 212.32,55.3 212.32,55.01 212.16,54.85 211.84,54.85 211.77,54.77 211.77,54.62 211.84,54.54 212.16,54.54 212.34,54.37 212.34,54.08 212.16,53.91 211.84,53.91 211.77,53.83 211.77,53.68 211.84,53.6 212.23,53.6 212.4,53.43 212.4,53.14 212.23,52.97 211.84,52.97 211.77,52.89 211.77,52.74 211.84,52.67 212.07,52.67 212.34,52.4 212.34,51.94 213.23,51.05 213.23,45.21 213.23,45.21
  LAY6 w0.087: 213.23,45.21 213.85,44.59 213.85,39.81 208.54,34.51 208.54,29.77 205.04,26.27 205.04,23.44 204.41,22.82 204.41,21.47 205.03,20.85 205.03,19.29 204.78,19.04 204.54,19.04 v2(204.36,18.86)
M_B_CLK_DDR_DP<1>: length 53.4
  TOP w0.076: CN1.138 205.11,14.91 204.95,15.08 204.95,15.75 205.14,15.95 205.42,15.95 v2(205.62,15.75) ; U1.AP46 213.09,59.9 213.41,59.64 v2(213.42,59.51)
  LAY6 w0.076: 214.08,45.24 214.08,45.24 214.08,50.98 214.21,51.11 214.21,55.39 213.02,56.58 213.02,59.71 213.12,59.81 213.29,59.81 213.42,59.68 v2(213.42,59.51)
  LAY6 w0.087: v2(205.62,15.75) 205.89,16.02 206.18,16.02 206.34,16.19 206.34,17 205.42,17.93 205.42,22.06 205.72,22.36 205.72,23.44 205.73,23.44 205.73,25.97 209.3,29.54 209.3,34.31 214.39,39.4 214.39,44.93 214.08,45.24
M_B_CS*<0>: length 53.2
  TOP w0.076: U1.BB42 209.91,54.79 209.91,53.81 210.05,53.67 210.05,53.45 210.18,53.32 210.18,52.18 210.24,52.12 210.47,52.12 210.54,52.19 v2(210.54,52.3)
  TOP w0.153: v2(197.87,18.13) 198.32,17.69 199.04,17.69 200.36,19.01 CN1.149
  LAY6 w0.076: 208.84,45.03 209.11,45.3 209.11,51.08 210.33,52.3 v2(210.54,52.3)
  LAY6 w0.137: v2(197.87,18.13) 197.87,17.04 197.63,16.8 197.17,16.8 196.9,17.07 196.9,23.86 196.36,24.39 196.36,27.16 202.21,33.02 202.21,36.18 208.84,42.81 208.84,45.03
M_B_CS*<1>: length 54.6
  TOP w0.076: 209.84,51.24 209.84,53.19 209.72,53.31 209.72,53.53 209.58,53.67 209.58,54.42 209.52,54.48 209.52,54.97 209.53,54.99 209.62,55.21 209.68,55.37 209.68,55.86 U1.AY42
  TOP w0.102: 209.84,51.24 209.84,50.31 210,50.15 v2(210.42,50.15)
  TOP w0.153: v2(197.86,20.03) 198.36,20.53 CN1.157
  LAY6 w0.076: 209.86,44.29 209.62,44.52 209.62,50.47 209.78,50.63 210.07,50.63 210.42,50.28 v2(210.42,50.15)
  LAY6 w0.137: 209.86,44.29 209.86,42.57 203.14,35.86 203.14,32.63 198.42,27.91 198.42,20.52 198.93,20.01 198.93,16.23 198.65,15.95 198.19,15.95 198,16.14 198,16.45 198.27,16.73 198.27,19.62 v2(197.86,20.03)
M_B_DQ<0>: length 60
  TOP w0.076: U1.AY39 208.68,55.92 208.94,55.65 208.94,55.37 209.05,55.12 209.05,55.1 209.11,54.97 209.11,54.57 209.05,54.51 209.05,53.66 208.9,53.51 208.9,52.92 209.05,52.76 209.05,51.12 209.17,50.99 209.17,50.86 209.17,48.23 208.67,47.74 208.67,46.97 v2(207.97,46.27)
  TOP w0.129: CN1.8 237.61,15.25 v2(238.11,15.75)
  LAY3 w0.076: 207.97,45.5 v2(207.97,46.27)
  LAY3 w0.087: v2(238.11,15.75) 238.05,15.75 237.7,16.1 237.7,16.68 236.3,18.08 236.3,24.12 223.42,37 216.46,37 210.09,43.38
  LAY3 w0.091: 210.09,43.38 209.74,43.73
  LAY3 w0.094: 209.74,43.73 207.97,45.5
M_B_DQ<1>: length 58.1
  TOP w0.076: v2(207.97,52.23) 207.58,52.62 207.58,54.39 207.78,54.59 207.78,54.96 207.73,55.08 207.73,55.2 207.8,55.41 207.8,55.56 207.74,55.72 207.74,55.9 207.76,55.94 207.76,56.51 208.02,56.78 U1.AW39
  TOP w0.129: CN1.7 237.86,20.53 v2(237.37,20.03)
  LAY3 w0.076: 208.78,45.94 208.78,51.41 v2(207.97,52.23)
  LAY3 w0.087: 210.99,43.73 211.17,43.73 213.99,40.92 216.91,40.92 216.99,40.83 216.99,40.65 217.08,40.56 217.25,40.56 217.34,40.65 217.34,40.83 217.43,40.92 217.6,40.92 217.69,40.83 217.69,40.65 217.77,40.56 217.95,40.56 218.03,40.65 218.03,40.83 218.12,40.92 218.29,40.92 218.38,40.83 218.38,40.65 218.47,40.56 218.64,40.56 218.73,40.65 218.73,40.83 218.81,40.92 220.85,40.92 237.72,24.04 237.72,20.29 237.46,20.03 v2(237.37,20.03)
  LAY3 w0.091: 210.99,43.73 208.78,45.94
M_B_DQ<2>: length 60.3
  TOP w0.076: v2(207.97,51.58) 207.41,52.13 207.41,54.46 207.62,54.66 207.62,54.93 207.56,55.05 207.56,55.19 207.62,55.42 207.62,55.55 207.55,55.77 207.55,56.02 U1.AY37
  TOP w0.129: v2(234.36,20.62) 234.37,20.62 CN1.21
  LAY3 w0.076: v2(207.97,51.58) 206.83,50.45 206.83,48.36 207.16,48.03 207.16,44.54
  LAY3 w0.087: 207.16,44.54 216.27,35.43 216.9,35.43 216.96,35.49 216.96,35.89 217.05,35.97 217.22,35.97 217.31,35.89 217.31,35.54 217.42,35.43 217.6,35.43 217.66,35.49 217.66,35.89 217.74,35.97 217.92,35.97 218,35.89 218,35.54 218.12,35.43 218.29,35.43 218.35,35.49 218.35,35.89 218.44,35.97 218.61,35.97 218.7,35.89 218.7,35.54 218.81,35.43 218.98,35.43 219.04,35.49 219.04,35.89 219.13,35.97 219.3,35.97 219.39,35.89 219.39,35.54 219.5,35.43 219.68,35.43 219.74,35.49 219.74,35.89 219.82,35.97 220,35.97 220.08,35.89 220.08,35.54 220.19,35.43 220.37,35.43 220.43,35.49 220.43,35.89 220.52,35.97 220.69,35.97 220.78,35.89 220.78,35.54 220.89,35.43 221.06,35.43 221.12,35.49 221.12,35.89 221.21,35.97 221.38,35.97 221.47,35.89 221.47,35.54 221.58,35.43 221.75,35.43 221.82,35.49 221.82,35.89 221.9,35.97 222.07,35.97 222.16,35.89 222.16,35.54 222.27,35.43 223.16,35.43 234.39,24.21 234.39,20.64 v2(234.36,20.62)
M_B_DQ<3>: length 60.8
  TOP w0.076: v2(206.19,48.33) 206.92,49.06 206.92,54.46 206.92,54.46 206.92,55.48 207.14,55.7 207.14,56.25 207.45,56.56 U1.AW37
  TOP w0.129: v2(234.36,19.45) 234.53,19.45 235.37,20.28 CN1.17
  LAY3 w0.076: 206.97,44.25 206.97,47.55 v2(206.19,48.33)
  LAY3 w0.087: v2(234.36,19.45) 233.95,19.86 233.95,24.15 223.35,34.76 222.76,34.76 222.69,34.83 222.69,34.92 222.6,35.01 222.43,35.01 222.34,34.92 222.34,34.85 222.25,34.76 222.07,34.76 221.99,34.84 221.99,35.01 221.9,35.1 221.73,35.1 221.64,35.01 221.64,34.84 221.55,34.76 221.38,34.76 221.29,34.84 221.29,35.01 221.21,35.1 221.03,35.1 220.95,35.01 220.95,34.84 220.86,34.76 220.69,34.76 220.6,34.84 220.6,35.01 220.51,35.1 220.34,35.1 220.25,35.01 220.25,34.84 220.17,34.76 219.99,34.76 219.91,34.84 219.91,35.01 219.82,35.1 219.65,35.1 219.56,35.01 219.56,34.84 219.47,34.76 219.3,34.76 219.21,34.84 219.21,35.01 219.13,35.1 218.95,35.1 218.87,35.01 218.87,34.84 218.78,34.76 218.61,34.76 218.52,34.84 218.52,35.01 218.43,35.1 218.26,35.1 218.17,35.01 218.17,34.84 218.09,34.76 217.91,34.76 217.83,34.84 217.83,35.01 217.74,35.1 217.57,35.1 217.48,35.01 217.48,34.84 217.39,34.76 217.22,34.76 217.13,34.84 217.13,35.01 217.05,35.1 216.88,35.1 216.79,35.01 216.79,34.84 216.7,34.76 216.46,34.76 206.97,44.25
M_B_DQ<4>: length 58.6
  TOP w0.076: U1.BB39 208.71,54.79 208.71,53.79 208.57,53.65 208.57,52.78 208.72,52.63 208.72,50.98 208.82,50.88 208.82,49.18 v2(207.97,48.33)
  TOP w0.129: CN1.3 238.86,20.22 237.51,18.86 v2(237.37,18.86)
  LAY3 w0.076: 208.57,45.85 208.57,47.72 v2(207.97,48.33)
  LAY3 w0.087: v2(237.37,18.86) 237.19,18.86 236.98,19.07 236.98,24.3 221.11,40.17 216.38,40.17 216.29,40.25 216.29,40.49 216.21,40.57 216.03,40.57 215.95,40.49 215.95,40.25 215.86,40.17 215.69,40.17 215.6,40.25 215.6,40.51 215.51,40.6 215.34,40.6 215.25,40.51 215.25,40.25 215.17,40.17 214.99,40.17 214.91,40.25 214.91,40.51 214.82,40.6 214.65,40.6 214.56,40.51 214.56,40.25 214.47,40.17 214.25,40.17 210.8,43.62
  LAY3 w0.091: 208.57,45.85 210.8,43.62
M_B_DQ<5>: length 59.1
  TOP w0.076: U1.BA39 208.68,55.33 208.82,55.18 208.82,55.18 208.82,55.18 208.94,54.93 208.94,54.63 208.89,54.58 208.89,53.73 208.73,53.58 208.73,52.85 208.88,52.7 208.88,51.05 209.01,50.93 209.01,48.72 v2(207.97,47.68)
  TOP w0.129: v2(238.11,16.92) 238.61,16.42 CN1.4
  LAY3 w0.076: v2(207.97,47.68) 208.39,47.26 208.39,45.6
  LAY3 w0.087: v2(238.11,16.92) 236.63,18.4 236.63,24.21 220.99,39.86 214.13,39.86 210.39,43.59
  LAY3 w0.091: 208.39,45.6 210.39,43.59
M_B_DQ<6>: length 59.7
  TOP w0.076: U1.BA37 207.35,55.26 207.08,55 207.08,54.53 207.08,47.8 v2(206.19,46.9)
  TOP w0.129: CN1.16 235.61,16.42 v2(235.11,16.92)
  LAY3 w0.076: v2(206.19,46.9) 206.76,46.33 206.76,44.33
  LAY3 w0.087: v2(235.11,16.92) 234.47,16.92 234.19,17.19 234.19,17.37 234.28,17.45 234.41,17.45 234.5,17.54 234.5,17.71 234.41,17.8 234.28,17.8 234.19,17.89 234.19,18.06 234.28,18.15 234.41,18.15 234.5,18.23 234.5,18.41 234.41,18.49 234.28,18.49 234.19,18.58 234.19,19 233.64,19.55 233.64,24.03 223.22,34.45 216.33,34.45 206.6,44.18 206.76,44.33
M_B_DQ<7>: length 58.8
  TOP w0.076: U1.BB37 207.35,54.63 207.25,54.53 207.25,47.25 v2(206.19,46.19)
  TOP w0.129: v2(235.11,15.75) 234.61,15.25 CN1.20
  LAY3 w0.076: 206.2,44.1 206.2,44.24 206.58,44.62 206.58,45.8 v2(206.19,46.19)
  LAY3 w0.087: v2(235.11,15.75) 234.33,15.75 233.9,16.18 233.9,18.83 233.31,19.42 233.31,23.93 223.14,34.1 215.8,34.1 206.2,43.7 206.2,44.1
M_B_DQ<8>: length 61.2
  TOP w0.076: v2(206.19,50.28) 205.63,50.84 205.63,52.48 206.26,53.11 206.26,54.15 206.05,54.36 206.05,54.93 206.09,55.02 206.09,55.03 206.09,55.28 206.05,55.37 206.05,55.57 206.08,55.66 206.12,55.76 206.12,56.02 U1.AY35
  TOP w0.129: v2(232.86,18.86) 233.12,18.86 233.37,19.11 CN1.25
  LAY3 w0.076: v2(206.19,50.28) 205.62,49.71 205.62,48.65 205.61,48.64 205.61,44.88 205.49,44.76
  LAY3 w0.087: 205.49,44.76 205.49,43.2 215.59,33.1 222.45,33.1 229.56,25.99 229.68,25.99 229.74,26.05 229.86,26.05 229.98,25.93 229.98,25.8 229.93,25.75 229.93,25.62 230.05,25.5 230.17,25.5 230.23,25.56 230.35,25.56 230.47,25.43 230.47,25.31 230.42,25.26 230.42,25.13 230.54,25.01 230.66,25.01 230.72,25.07 230.84,25.07 230.96,24.94 230.96,24.82 230.91,24.77 230.91,24.64 231.03,24.52 231.15,24.52 231.21,24.58 231.33,24.58 231.45,24.45 231.45,24.33 231.4,24.28 231.4,24.15 232.15,23.4 232.15,23.18 232.06,23.09 231.6,23.09 231.51,23.01 231.51,22.83 231.6,22.75 232.06,22.75 232.15,22.66 232.15,22.49 232.06,22.4 231.6,22.4 231.51,22.31 231.51,22.14 231.6,22.05 232.06,22.05 232.15,21.97 232.15,21.79 232.08,21.72 231.88,21.72 231.79,21.63 231.79,21.46 231.89,21.36 232.06,21.36 232.15,21.27 232.15,19.01 232.29,18.86 v2(232.86,18.86)
